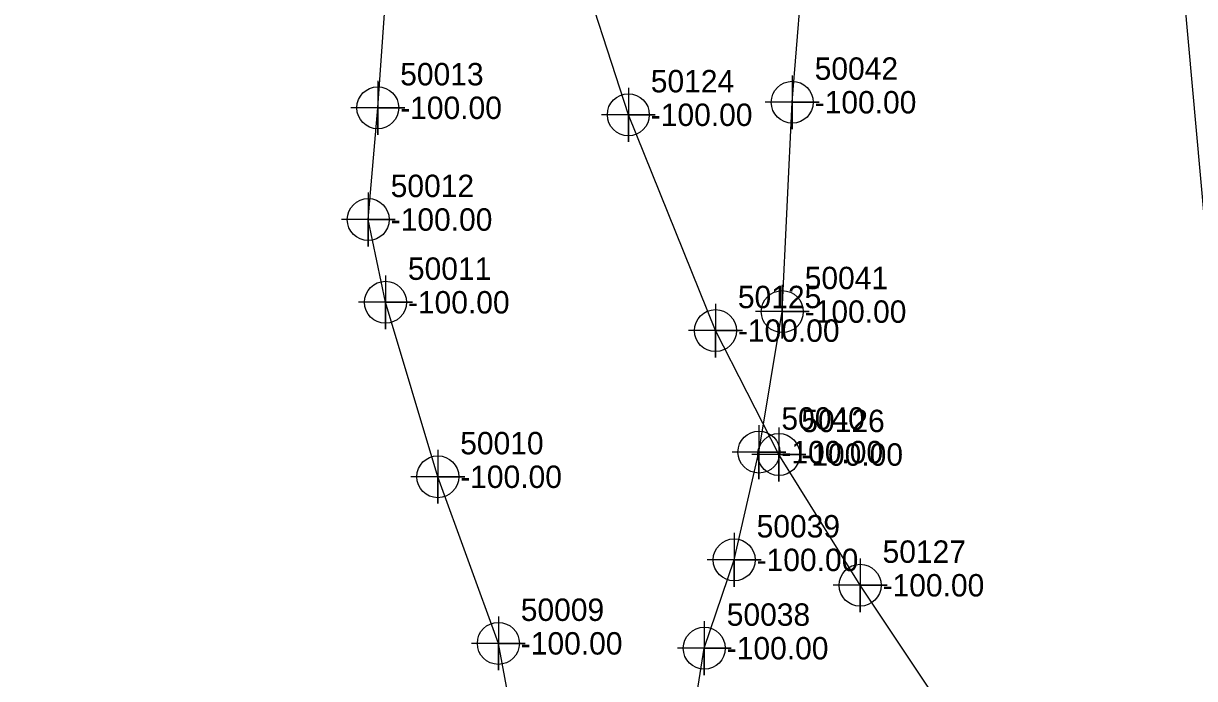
# Model space of a CAD drawing. Extents: x 2083698 to 2094313, y 743246 to 752873.
# Drawn here: x 2090977 to 2091107.5, y 749899.9 to 749973 of the extents above; entities that cross this region are included whole.
import ezdxf

# ---------------------------------------------------------------- set-up
doc = ezdxf.new("R2010")
doc.units = 0
for name, color, linetype in [('COGO Default Point Number', 7, 'Continuous'), ('Default Symbol CELL', 7, 'Continuous'), ('Default Symbol Cogo Number', 7, 'Continuous'), ('Exist Property Iron Pin Leader', 7, 'Continuous'), ('Exist Property Iron Pin Text', 7, 'Continuous'), ('Exist Property Line', 7, 'Continuous'), ('Exist Property Line Leader', 7, 'Continuous'), ('Exist Property Monument Text', 7, 'Continuous'), ('Exist Right of Way Line', 7, 'Continuous'), ('Exist Utilities Power UG Cable SUE LOS B', 7, 'Continuous'), ('Exist Utilities Power UG Cable SUE LOS C', 7, 'Continuous'), ('Exist Utilities TV UG Cable SUE LOS B', 7, 'Continuous'), ('Exist Utilities Water UG Line SUE LOS B', 7, 'Continuous')]:
    doc.layers.add(name, color=color, linetype=linetype)

msp = doc.modelspace()

# ---------------------------------------------------------------- linework, layer by layer
at = {"layer": 'COGO Default Point Number'}
for points in [[(2091044.38, 749965.76), (2091044.38, 749959.76), (2091044.38, 749962.76), (2091047.38, 749962.76), (2091041.38, 749962.76)], [(2091054.09, 749941.69), (2091054.09, 749935.69), (2091054.09, 749938.69), (2091057.09, 749938.69), (2091051.09, 749938.69)], [(2091061.16, 749927.87), (2091061.16, 749921.87), (2091061.16, 749924.87), (2091064.16, 749924.87), (2091058.16, 749924.87)], [(2091070.22, 749913.29), (2091070.22, 749907.29), (2091070.22, 749910.29), (2091073.22, 749910.29), (2091067.22, 749910.29)]]:
    msp.add_lwpolyline(points, dxfattribs=at)
for centre in [(2091044.38, 749962.76), (2091054.09, 749938.69), (2091061.16, 749924.87), (2091070.22, 749910.29)]:
    msp.add_circle(centre, 2.34, dxfattribs=at)
at = {"layer": 'Exist Property Iron Pin Text'}
for points in [[(2091016.45, 749966.54), (2091016.45, 749960.54), (2091016.45, 749963.54), (2091019.45, 749963.54), (2091013.45, 749963.54)], [(2091015.39, 749954.08), (2091015.39, 749948.08), (2091015.39, 749951.08), (2091018.39, 749951.08), (2091012.39, 749951.08)], [(2091017.31, 749944.85), (2091017.31, 749938.85), (2091017.31, 749941.85), (2091020.31, 749941.85), (2091014.31, 749941.85)], [(2091023.14, 749925.39), (2091023.14, 749919.39), (2091023.14, 749922.39), (2091026.14, 749922.39), (2091020.14, 749922.39)], [(2091029.89, 749906.81), (2091029.89, 749900.81), (2091029.89, 749903.81), (2091032.89, 749903.81), (2091026.89, 749903.81)]]:
    msp.add_lwpolyline(points, dxfattribs=at)
for centre in [(2091016.45, 749963.54), (2091015.39, 749951.08), (2091017.31, 749941.85), (2091023.14, 749922.39), (2091029.89, 749903.81)]:
    msp.add_circle(centre, 2.34, dxfattribs=at)
at = {"layer": 'Exist Property Line Leader'}
for points in [[(2091062.65, 749967.16), (2091062.65, 749961.16), (2091062.65, 749964.16), (2091065.65, 749964.16), (2091059.65, 749964.16)], [(2091061.54, 749943.81), (2091061.54, 749937.81), (2091061.54, 749940.81), (2091064.54, 749940.81), (2091058.54, 749940.81)], [(2091058.94, 749928.14), (2091058.94, 749922.14), (2091058.94, 749925.14), (2091061.94, 749925.14), (2091055.94, 749925.14)], [(2091056.18, 749916.12), (2091056.18, 749910.12), (2091056.18, 749913.12), (2091059.18, 749913.12), (2091053.18, 749913.12)], [(2091052.85, 749906.27), (2091052.85, 749900.27), (2091052.85, 749903.27), (2091055.85, 749903.27), (2091049.85, 749903.27)]]:
    msp.add_lwpolyline(points, dxfattribs=at)
for centre in [(2091062.65, 749964.16), (2091061.54, 749940.81), (2091058.94, 749925.14), (2091056.18, 749913.12), (2091052.85, 749903.27)]:
    msp.add_circle(centre, 2.34, dxfattribs=at)
at = {"layer": 'Exist Utilities Power UG Cable SUE LOS B'}
msp.add_lwpolyline([(2091031.73, 749894.02), (2091029.89, 749903.81), (2091023.14, 749922.39), (2091017.31, 749941.85), (2091015.39, 749951.08), (2091016.45, 749963.54), (2091017.85, 749983.03), (2091019, 749991.54), (2091025.29, 750018.88), (2091031.82, 750047.51), (2091037, 750068.33)], dxfattribs=at)
at = {"layer": 'Exist Utilities Power UG Cable SUE LOS C'}
msp.add_lwpolyline([(2091181.56, 749137.25), (2091102.57, 750018.32), (2091019.27, 750921.35), (2090968.35, 751478.78)], dxfattribs=at)
at = {"layer": 'Exist Utilities TV UG Cable SUE LOS B'}
msp.add_lwpolyline([(2091056.04, 749823.91), (2091050.45, 749829.11), (2091049.76, 749829.88), (2091050.72, 749849.32), (2091050.12, 749868.64), (2091049.05, 749879.27), (2091052.85, 749903.27), (2091056.18, 749913.12), (2091058.94, 749925.14), (2091061.54, 749940.81), (2091062.65, 749964.16), (2091064.58, 749987.99), (2091073.97, 750026.86), (2091083.34, 750064.17), (2091096.21, 750101.65), (2091110.09, 750137.04), (2091111.02, 750138.39), (2091114.18, 750141.15), (2091117.92, 750143.91), (2091124.2, 750146.07)], dxfattribs=at)
at = {"layer": 'Exist Utilities Water UG Line SUE LOS B'}
msp.add_lwpolyline([(2091080.76, 749894.46), (2091070.22, 749910.29), (2091061.16, 749924.87), (2091054.09, 749938.69), (2091044.38, 749962.76), (2091038.26, 749981.68), (2091038.08, 750001.58), (2091039.14, 750015.58), (2091040.91, 750046.39), (2091044.3, 750082.04), (2091047.29, 750103.42), (2091050.31, 750113.65), (2091067.52, 750142.1), (2091073.52, 750153.34), (2091084.4, 750173), (2091091.41, 750187.63), (2091099.83, 750208.35), (2091105.45, 750222.47)], dxfattribs=at)

# ---------------------------------------------------------------- texts
at = {"layer": 'Default Symbol CELL'}
for s, p in [('50042', (2091065.15, 749966.66)), ('50041', (2091064.04, 749943.31)), ('50040', (2091061.44, 749927.64)), ('50039', (2091058.68, 749915.62)), ('50038', (2091055.35, 749905.77))]:
    msp.add_text(s, height=2.5, dxfattribs=at).set_placement(p)
at = {"layer": 'Default Symbol Cogo Number'}
for p in [(2091065.15, 749962.91), (2091064.04, 749939.56), (2091061.44, 749923.89), (2091058.68, 749911.87), (2091055.35, 749902.02)]:
    msp.add_text('-100.00', height=2.5, dxfattribs=at).set_placement(p)
at = {"layer": 'Exist Property Iron Pin Leader'}
for s, p in [('50013', (2091018.95, 749966.04)), ('50012', (2091017.89, 749953.58)), ('50011', (2091019.81, 749944.35)), ('50010', (2091025.64, 749924.89)), ('50009', (2091032.39, 749906.31))]:
    msp.add_text(s, height=2.5, dxfattribs=at).set_placement(p)
at = {"layer": 'Exist Property Line'}
for p in [(2091046.88, 749961.51), (2091056.59, 749937.44), (2091063.66, 749923.62), (2091072.72, 749909.04)]:
    msp.add_text('-100.00', height=2.5, dxfattribs=at).set_placement(p)
at = {"layer": 'Exist Property Monument Text'}
for p in [(2091018.95, 749962.29), (2091017.89, 749949.83), (2091019.81, 749940.6), (2091025.64, 749921.14), (2091032.39, 749902.56)]:
    msp.add_text('-100.00', height=2.5, dxfattribs=at).set_placement(p)
at = {"layer": 'Exist Right of Way Line'}
for s, p in [('50124', (2091046.88, 749965.26)), ('50125', (2091056.59, 749941.19)), ('50126', (2091063.66, 749927.37)), ('50127', (2091072.72, 749912.79))]:
    msp.add_text(s, height=2.5, dxfattribs=at).set_placement(p)

doc.saveas('drawing.dxf')
